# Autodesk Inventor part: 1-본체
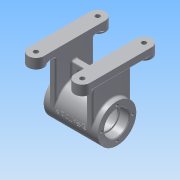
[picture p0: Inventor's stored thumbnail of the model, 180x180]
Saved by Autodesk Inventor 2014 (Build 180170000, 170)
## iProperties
Created: 2015-11
Part Number: 1-본체
Material: 알루미늄 6061
Document SubType Name: Modeling
Designer: 103-19
Density: 2.71 g/cm^3
Appearance: 알루미늄 - 평지
Mass: 357.834 g
Surface Area: 460.865 cm^2
Volume: 132.042 cm^3
Author: 103-19
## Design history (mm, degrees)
sketch "스케치1"
  geometry: L1 (0, 0)-(-70, 0); L2 (0, 0)-(0, 25); L3 (0, 25)-(-70, 25); L4 (-70, 25)-(-70, 0)
  constraints: 8 end point, 2 perpendicular, 1 horizontal, 1 parallel
  dimensions: "d0" = 70 distance of L1.start L1.end; "d1" = 50 diameter of L3 L1
revolve "회전1" sketch "스케치1" stored, may be unused: angle "d2" = 90 deg
node "작업 평면1"
sketch "스케치2"
  geometry: L1 (-5, 50)-(15, 50); L2 (15, 50)-(15, -50); L3 (15, -50)-(-5, -50); L4 (-5, -50)-(-5, 50); L5 (-5, 50)-(15, -50); L6 (15, 50)-(-5, -50); L7 (55, 50)-(75, 50); L8 (75, 50)-(75, -50); L9 (75, -50)-(55, -50); L10 (55, -50)-(55, 50); L11 (55, 50)-(75, -50); L12 (75, 50)-(55, -50); L13 (70, 25)-(0, 25) reference; L14 (35, 25)-(35, -25); L15 (0, 0)-(75, 0); L16 (0, 25)-(0, -25) reference; L17 (70, 25)-(70, -25) reference; L18 (70, -25)-(0, -25) reference; 2 further points
  constraints: 28 end point, 7 midpoint, 4 parallel, 4 perpendicular, 2 equal length, 2 horizontal, 1 collinear
  dimensions: "d4" = 20 distance of L1.start L1.end; "d7" = 80 distance between parallel lines of L8 L4; "d8" = 40 distance between parallel lines of L14 L4; "d9" = 100 distance of L3.end L1.start; "d10" = 50 distance between parallel lines of L15 L1
extrude "돌출1" join sketch "스케치2" distance "d11" = 10; taper "d12" = 0 deg
fillet "모깎기1" dims "d13" = 10
sketch "스케치3"
  geometry: L1 (55, -40)-(55, 40) reference; L2 (75, 40)-(75, -40) reference; C1 r 10 at (5, 40); C2 r 10 at (65, 40); C3 r 10 at (65, -40); C4 r 10 at (5, -40); A1 r 10 centre (5, -40) between (-5, -40) and (15, -40) reference; A2 r 10 centre (5, 40) between (15, 40) and (-5, 40) reference; A3 r 10 centre (65, -40) between (55, -40) and (75, -40) reference; A4 r 10 centre (65, 40) between (75, 40) and (55, 40) reference; 1 further point
  constraints: 4 centre point, 4 coincident, 4 concentric
extrude "돌출2" join sketch "스케치3" distance "d14" = 3; taper "d15" = 0 deg
sketch "스케치4"
  geometry: L1 (-10, 0)-(-10, 80) reference; L2 (-68, 15)-(-10, 15); L3 (-68, 65)-(-10, 65); A1 r 25 centre (-68, 40) between (-68, 15) and (-68, 65) reference; 1 further point
  constraints: 4 end point, 2 perpendicular, 2 point on circle, 2 point on line, 2 tangent
extrude "돌출3" join sketch "스케치4" distance "d16" = 8; taper "d17" = 0 deg
node "작업 평면2"
hole "구멍1" diameter "d20" = 28; stored, may be unused: countersink angle "d24" = 90 deg, drill point angle "d26" = 0 deg; dims "d18" = 10, "d19" = 10, "d21" = 6, "d22" = 32, "d23" = 12, "d25" = 14
hole "구멍2" diameter "d29" = 42; stored, may be unused: countersink angle "d33" = 90 deg, drill point angle "d35" = 0 deg; dims "d27" = 10, "d28" = 10, "d30" = 6, "d31" = 32, "d32" = 12, "d34" = 42
sketch "스케치5" dims "d36" = 40
  geometry: C1 r 16 at (0, 0) reference; C2 r 25 at (0, 0) reference; 5 further points
  constraints: 2 vertical alignment, 1 coincident, 7 other
  dimensions: "d39" = 360 deg dimension on C1.centre point (0, 20) (derived)
hole "구멍3" sketch "스케치5" at (0, 20), (-20, 0), (0, -20), (20, 0) diameter "d41" = 3.242; stored, may be unused: countersink angle "d45" = 90 deg, drill point angle "d47" = 118 deg; dims "d42" = 8, "d43" = 32, "d44" = 12, "d46" = 10
node "작업 평면3"
sketch "스케치6"
  geometry: L1 (55, 0)-(55, 58) reference; L2 (15, 0)-(15, 58) reference; L3 (55, 12)-(15, 12); L4 (55, 45)-(15, 45); L5 (70, 25)-(0, 25) reference; 1 further point
  constraints: 4 end point, 4 point on line, 2 perpendicular
  dimensions: "d82" = 20 distance between parallel lines of L4 L5; "d83" = 33 distance between parallel lines of L4 L3
extrude "돌출4" join sketch "스케치6" stored distance "d53" = 8; taper "d54" = 0 deg
sketch "스케치8"
  geometry: C1 r 10 at (0, 0) reference; C2 r 10 at (0, 80) reference; C3 r 10 at (60, 80) reference; C4 r 10 at (60, 0) reference; 5 further points
  constraints: 4 coincident
hole "구멍4" sketch "스케치8" at (0, 80), (60, 80), (60, 0), (0, 0) diameter "d60" = 6; stored, may be unused: countersink angle "d64" = 90 deg, drill point angle "d66" = 0 deg; dims "d61" = 8, "d62" = 12, "d63" = 4, "d65" = 4
chamfer "모따기1" distance "d67" = 1; stored, may be unused: second distance "d68" = 2, angle "d69" = 45 deg
fillet "모깎기2" dims "d70" = 0.3
fillet "모깎기3" dims "d71" = 2
fillet "모깎기4" dims "d72" = 2
fillet "모깎기5" dims "d73" = 2
fillet "모깎기6" dims "d74" = 2
node "작업 평면4"
sketch "스케치9"
  geometry: L1 (-35, -25)-(35, -25) reference; 2 further points
  constraints: 1 other
  dimensions: "d75" = 35 distance of point (0, 0) point (35, 0); "d76" = 25 distance from line of point (0, 0) L1
feature "엠보싱1" sketch "스케치9" dims "d77" = 0.5, "d78" = 0
node "작업 평면5"
sketch "스케치10"
  geometry: C1 r 14 at (0, 0) reference; C2 r 21 at (0, 0) reference; 1 further point
extrude "돌출6" cut sketch "스케치10" stored distance "d84" = 42; taper "d85" = 0 deg
sketch "스케치11"
  geometry: L1 (-55, 24.678)-(-55, 45) reference; L2 (-43, 38.5)-(-27, 38.5); L3 (-27, 31.5)-(-43, 31.5); L4 (-70, -25)-(0, -25) reference; L5 (0, -25)-(0, 25) reference; L6 (-75, 68)-(-55, 68) reference; A1 r 3.5 centre (-27, 35) between (-27, 31.5) and (-27, 38.5); A2 r 3.5 centre (-43, 35) between (-43, 38.5) and (-43, 31.5); 3 further points
  constraints: 4 end point, 4 point on circle, 4 tangent, 2 centre point, 2 midpoint, 1 parallel, 1 perpendicular, 1 vertical alignment
  dimensions: "d86" = 23 dimension on A1 A2; "d87" = 7 distance between parallel lines of L3 L2; "d88" = 33 distance from line of A2.centre L6
extrude "돌출7" cut sketch "스케치11" stored distance "d89" = 42; taper "d90" = 0 deg
fillet "모깎기10" dims "d91" = 2
fillet "모깎기11" dims "d92" = 2
fillet "모깎기12" dims "d93" = 2
fillet "모깎기13" dims "d94" = 3
fillet "모깎기14" dims "d95" = 0.3
chamfer "모따기2" distance "d96" = 1; stored, may be unused: second distance "d97" = 2, angle "d98" = 45 deg
node "작업 평면7"
sketch "스케치12"
  geometry: L1 (70, 25)-(0, 25) reference; L2 (70, 25)-(70, -25) reference; C1 r 6 at (35, 0); 1 further point
  constraints: 1 centre point, 1 horizontal alignment
  dimensions: "d100" = 35 distance from line of C1.centre L2; "d101" = 12 diameter of C1
extrude "돌출8" join sketch "스케치12" stored distance "d102" = 42; taper "d103" = 0 deg
hole "구멍5" diameter "d106" = 5.188; stored, may be unused: countersink angle "d110" = 90 deg, drill point angle "d112" = 0 deg; dims "d107" = 8, "d108" = 12, "d109" = 4, "d111" = 4, "d132" = 10, "d133" = 10
node "작업 평면8"
sketch "스케치13"
  geometry: L1 (0, 0)-(14, 24.249); 2 further points
  constraints: 2 end point, 2 vertical alignment, 1 other
  dimensions: "d114" = 28 distance of L1.start L1.end; "d115" = 30 deg dimension on point (0, 0) L1.end point (0, 14)
node "작업 평면9"
sketch "스케치14"
  geometry: C1 r 6 at (0, 0); 2 further points
  constraints: 1 centre point, 1 coincident
  dimensions: "d116" = 12 diameter of C1
extrude "돌출9" join sketch "스케치14" stored distance "d117" = 42; taper "d118" = 0 deg
hole "구멍6" diameter "d121" = 5.188; stored, may be unused: countersink angle "d125" = 90 deg, drill point angle "d127" = 0 deg; dims "d122" = 8, "d123" = 12, "d124" = 4, "d126" = 4, "d130" = 10, "d131" = 10
fillet "모깎기15" dims "d128" = 2
fillet "모깎기16" dims "d129" = 2
node "솔리드1"
mirror "대칭1"
mirror "대칭2"
mirror "대칭3"
node "투영된 루프1"
node "투영된 루프2"
node "투영된 루프3"
node "투영된 루프4"
node "투영된 루프5"
node "투영된 루프6"
other parameters: "d3" = 68, "d48" = 0, "d99" = -28, "d113" = -35
